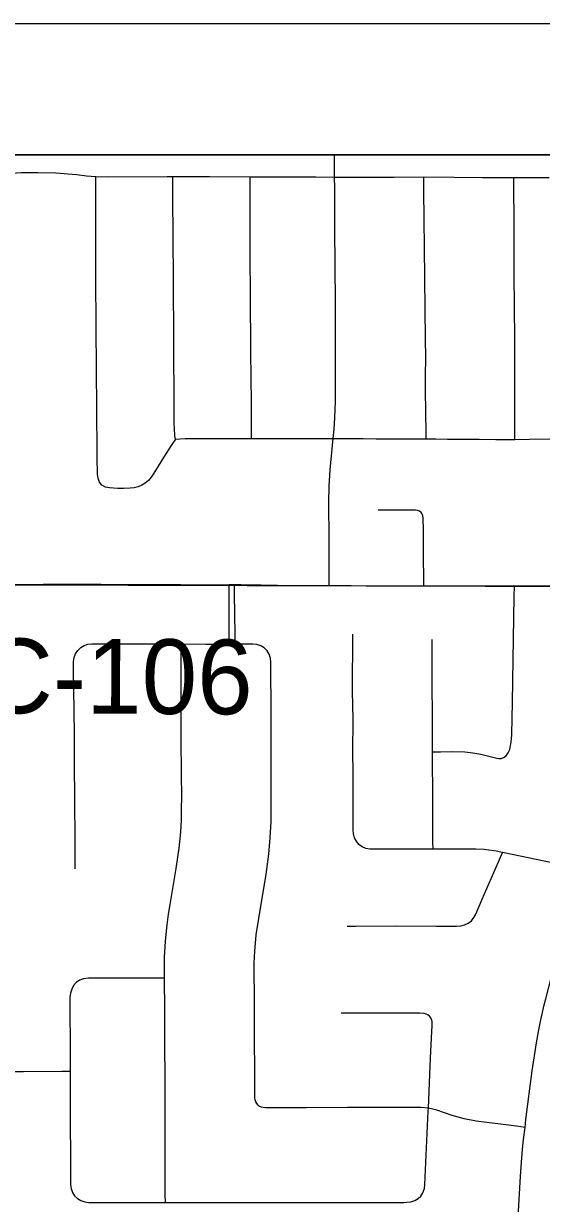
# Model space of a CAD drawing. Extents: x 0 to 34, y 0 to 22.
# Drawn here: x 19.27 to 19.665, y 15.179 to 16.078 of the extents above; entities that cross this region are included whole.
import ezdxf

# ---------------------------------------------------------------- set-up
doc = ezdxf.new("R2010")
doc.units = 0
for name, color, linetype in [('GM_X_City_Street', 7, 'Continuous'), ('GM_X_Corporation', 7, 'Continuous'), ('GM_X_County_Road', 7, 'Continuous'), ('GM_X_County_Road_Text', 7, 'Continuous'), ('GM_X_Section', 7, 'Continuous'), ('GM_X_Township_Road', 7, 'Continuous'), ('SH_Data', 7, 'Continuous')]:
    doc.layers.add(name, color=color, linetype=linetype)

msp = doc.modelspace()

# ---------------------------------------------------------------- linework, layer by layer
at = {"layer": 'GM_X_City_Street'}
for points in [[(19.503, 15.64975), (19.50299, 15.65426), (19.50287, 15.685), (19.50269, 15.71299), (19.50292, 15.72543), (19.50373, 15.73784), (19.50613, 15.76166), (19.50685, 15.76879), (19.50738, 15.77742), (19.50761, 15.78386), (19.5078, 15.78994), (19.5079, 15.79355), (19.50791, 15.80243), (19.50792, 15.82298), (19.50771, 15.86522), (19.50732, 15.92123), (19.50721, 15.9523), (19.50716, 15.96064), (19.50706, 15.97618), (19.50706, 15.97752)], [(19.29503, 15.96385), (19.29847, 15.96365), (19.30416, 15.96314), (19.31096, 15.96253), (19.31827, 15.96175), (19.32191, 15.96148), (19.32543, 15.96122), (19.33488, 15.96098), (19.37976, 15.96116), (19.38408, 15.96115), (19.4122, 15.96111), (19.44281, 15.96084), (19.44626, 15.96081), (19.49272, 15.96076), (19.50716, 15.96064), (19.5273, 15.96068), (19.54194, 15.96072), (19.55246, 15.96074), (19.57514, 15.96079), (19.59802, 15.96062), (19.61972, 15.96045), (19.64137, 15.96029), (19.64351, 15.96029), (19.67054, 15.96039)], [(19.38608, 15.76111), (19.38334, 15.75721), (19.37822, 15.74936), (19.36947, 15.73536), (19.36749, 15.73224), (19.36537, 15.72982), (19.36306, 15.72775), (19.36043, 15.72609), (19.35756, 15.72489), (19.35453, 15.72419), (19.35143, 15.72389), (19.34661, 15.72369), (19.3421, 15.72376), (19.3359, 15.72412), (19.33283, 15.72465), (19.3301, 15.7261), (19.32817, 15.72851), (19.32712, 15.73143), (19.32666, 15.73451), (19.32657, 15.73762), (19.32638, 15.74409), (19.32646, 15.7532), (19.3262, 15.78123), (19.32592, 15.81776), (19.32573, 15.84309), (19.32539, 15.88782), (19.32539, 15.90443), (19.32539, 15.91347), (19.32539, 15.92301), (19.32539, 15.95258), (19.32543, 15.96122)], [(19.38608, 15.76111), (19.38565, 15.76338), (19.38544, 15.76505), (19.38526, 15.76798), (19.3851, 15.77455), (19.38514, 15.78591), (19.38454, 15.88333), (19.38396, 15.94588), (19.38403, 15.95526), (19.38408, 15.96115)], [(19.44378, 15.76169), (19.4438, 15.7661), (19.44382, 15.7692), (19.44388, 15.77856), (19.44378, 15.79017), (19.44365, 15.80711), (19.44349, 15.82845), (19.44333, 15.84346), (19.44321, 15.85579), (19.44307, 15.86899), (19.44303, 15.87865), (19.44297, 15.89296), (19.4429, 15.91267), (19.44288, 15.92206), (19.44285, 15.93719), (19.44283, 15.95317), (19.44281, 15.96084)], [(19.57683, 15.76137), (19.57674, 15.76842), (19.57658, 15.77975), (19.57651, 15.78535), (19.57642, 15.79489), (19.57638, 15.79928), (19.57638, 15.80591), (19.57637, 15.81169), (19.57646, 15.821), (19.57602, 15.8582), (19.5758, 15.88606), (19.57557, 15.90491), (19.57548, 15.91214), (19.57534, 15.92324), (19.57523, 15.93451), (19.57514, 15.94483), (19.57514, 15.95556), (19.57514, 15.96079)], [(19.64441, 15.76096), (19.64439, 15.76874), (19.64433, 15.80603), (19.64423, 15.83714), (19.64405, 15.86202), (19.64383, 15.8869), (19.64387, 15.92422), (19.64355, 15.9555), (19.64351, 15.96029)], [(19.38608, 15.76111), (19.38936, 15.76156), (19.39329, 15.76171), (19.40848, 15.76177), (19.43972, 15.7617), (19.44378, 15.76169), (19.4555, 15.76166), (19.48952, 15.76166), (19.50613, 15.76166), (19.5105, 15.7617), (19.51682, 15.76167), (19.52882, 15.76161), (19.53869, 15.76156), (19.5553, 15.76148), (19.57683, 15.76137), (19.58408, 15.76133), (19.59312, 15.76128), (19.60415, 15.76121), (19.61713, 15.76113), (19.6298, 15.76105), (19.64441, 15.76096), (19.6555, 15.7612), (19.67096, 15.76134)], [(19.57501, 15.64949), (19.57497, 15.65305), (19.57491, 15.66135), (19.57488, 15.66498), (19.57482, 15.67216), (19.57477, 15.67915), (19.57472, 15.68428), (19.57466, 15.69172), (19.57459, 15.70116), (19.5743, 15.70274), (19.57402, 15.70372), (19.57361, 15.70455), (19.57304, 15.70537), (19.57163, 15.70633), (19.57029, 15.70681), (19.56861, 15.7071), (19.5597, 15.70715), (19.55402, 15.70718), (19.54721, 15.70722), (19.54032, 15.70727)], [(19.42683, 15.60519), (19.42683, 15.61102), (19.42685, 15.64383), (19.42685, 15.65044)], [(19.4315, 15.60519), (19.4314, 15.61241), (19.43099, 15.64336), (19.43089, 15.65046)], [(19.58171, 15.52319), (19.58766, 15.52327), (19.59694, 15.52338), (19.60622, 15.52307), (19.61237, 15.5224), (19.61847, 15.52129), (19.6305, 15.51833), (19.6321, 15.51812), (19.63389, 15.51821), (19.63561, 15.51884), (19.63765, 15.52024), (19.63934, 15.52249), (19.64046, 15.52493), (19.64109, 15.52806), (19.64153, 15.53053), (19.64181, 15.5332), (19.64203, 15.53628), (19.64248, 15.56106), (19.64387, 15.64155), (19.644, 15.64963)], [(19.69285, 15.43411), (19.68862, 15.43509), (19.67867, 15.4374), (19.66653, 15.43992), (19.64226, 15.44512), (19.63495, 15.44664), (19.63011, 15.44764), (19.6209, 15.44887), (19.61471, 15.44921), (19.58203, 15.44917), (19.57438, 15.44916), (19.53404, 15.44922), (19.53099, 15.44973), (19.52814, 15.45087), (19.52566, 15.4527), (19.52368, 15.45508), (19.52232, 15.45785), (19.52155, 15.46085), (19.52128, 15.46394), (19.52134, 15.50738), (19.52109, 15.52289), (19.52113, 15.54771), (19.52083, 15.56943), (19.5209, 15.61286)], [(19.58203, 15.44917), (19.582, 15.45472), (19.5818, 15.48859), (19.58172, 15.51939), (19.58171, 15.52319), (19.58168, 15.54096), (19.58145, 15.5841), (19.58134, 15.60874)], [(19.3097, 15.43416), (19.30956, 15.45577), (19.30939, 15.48672), (19.30918, 15.51456), (19.30923, 15.53622), (19.30891, 15.55478), (19.30874, 15.57024), (19.30847, 15.58569), (19.30843, 15.59188), (19.30892, 15.59492), (19.31001, 15.5978), (19.31168, 15.6004), (19.31387, 15.60256), (19.31651, 15.60415), (19.31943, 15.60508), (19.32249, 15.60544), (19.33486, 15.60537), (19.38738, 15.60537), (19.39048, 15.60535), (19.40902, 15.60527), (19.42683, 15.60519), (19.4315, 15.60519)], [(19.38083, 15.39972), (19.3819, 15.40688), (19.38658, 15.43443), (19.38887, 15.44979), (19.39007, 15.46216), (19.3905, 15.47147), (19.39064, 15.47937), (19.39074, 15.48933), (19.39066, 15.50566), (19.39042, 15.53358), (19.39038, 15.55486), (19.39035, 15.57376), (19.39046, 15.60201), (19.39048, 15.60535)], [(19.65204, 15.23735), (19.64562, 15.23814), (19.6148, 15.24195), (19.60566, 15.24374), (19.59671, 15.24628), (19.58497, 15.25038), (19.58199, 15.25127), (19.57855, 15.25194), (19.57279, 15.25255), (19.55725, 15.25258), (19.51683, 15.25235), (19.48575, 15.25232), (19.47331, 15.25227), (19.45461, 15.25216), (19.45288, 15.25237), (19.45157, 15.25272), (19.45008, 15.25333), (19.44892, 15.25424), (19.44784, 15.25553), (19.44712, 15.2567), (19.44656, 15.25824), (19.44636, 15.25969), (19.44633, 15.26592), (19.44635, 15.28146), (19.44617, 15.30321), (19.44608, 15.33118), (19.44595, 15.36227), (19.44634, 15.37158), (19.44755, 15.38395), (19.4494, 15.39624), (19.4551, 15.42996), (19.45709, 15.44537), (19.45815, 15.45775), (19.45872, 15.47017), (19.45891, 15.47979), (19.45887, 15.50125), (19.45875, 15.55098), (19.45861, 15.59138), (19.45824, 15.59446), (19.45731, 15.59742), (19.45573, 15.60007), (19.45353, 15.60225), (19.45089, 15.60383), (19.44796, 15.60478), (19.44488, 15.6052), (19.4315, 15.60519)], [(19.51677, 15.39045), (19.52294, 15.39056), (19.55376, 15.39062), (19.58458, 15.39058), (19.6, 15.39045), (19.60307, 15.39072), (19.60604, 15.39146), (19.60883, 15.39277), (19.61126, 15.39465), (19.61317, 15.39705), (19.61465, 15.39975), (19.61951, 15.41108), (19.63179, 15.43935), (19.63495, 15.44664)], [(19.3784, 15.18021), (19.3783, 15.18655), (19.37825, 15.18965), (19.37814, 15.24869), (19.37807, 15.27044), (19.37809, 15.28288), (19.37796, 15.2922), (19.378, 15.30463), (19.37783, 15.32639), (19.37768, 15.35087), (19.37765, 15.35437), (19.37768, 15.3667), (19.37837, 15.37919), (19.37962, 15.39154), (19.38083, 15.39972)], [(19.37768, 15.35087), (19.3718, 15.35089), (19.34388, 15.35097), (19.32528, 15.35079), (19.31985, 15.35079), (19.31599, 15.35033), (19.31309, 15.34929), (19.31055, 15.34757), (19.3085, 15.34527), (19.30705, 15.34255), (19.30615, 15.33959), (19.3057, 15.33653), (19.30555, 15.33031), (19.30585, 15.29623), (19.30578, 15.28005), (19.30577, 15.27761), (19.306, 15.25589), (19.30601, 15.20003), (19.30611, 15.19377), (19.30661, 15.1907), (19.30764, 15.18781), (19.30926, 15.18522), (19.31144, 15.1831), (19.31408, 15.18157), (19.31701, 15.18064), (19.32009, 15.18023), (19.3784, 15.18021), (19.44106, 15.1802), (19.46587, 15.1802), (19.49069, 15.18005), (19.52172, 15.18016), (19.54033, 15.18026), (19.55585, 15.18023), (19.55976, 15.18026), (19.56222, 15.18036), (19.56512, 15.1807), (19.56808, 15.18161), (19.57077, 15.18316), (19.57275, 15.18497), (19.57439, 15.18743), (19.57548, 15.19085), (19.57586, 15.19393), (19.57845, 15.24973), (19.57855, 15.25194), (19.57967, 15.27765), (19.58006, 15.29003), (19.58094, 15.30552), (19.58136, 15.31482), (19.58131, 15.31793), (19.58096, 15.31954), (19.58028, 15.3208), (19.57929, 15.322), (19.57807, 15.32291), (19.57673, 15.3236), (19.57519, 15.32399), (19.5721, 15.32432), (19.5121, 15.32427)], [(19.26064, 15.27981), (19.27032, 15.27996), (19.29948, 15.28004), (19.30578, 15.28005)]]:
    msp.add_lwpolyline(points, dxfattribs=at)
at = {"layer": 'GM_X_Corporation'}
msp.add_lwpolyline([(22.22398, 15.97752), (18.62557, 15.97752)], dxfattribs=at)
at = {"layer": 'GM_X_County_Road'}
for points in [[(19.25949, 15.65063), (19.28569, 15.65072), (19.32942, 15.6507), (19.37942, 15.6505), (19.38982, 15.65049)], [(19.38982, 15.65049), (19.41405, 15.65038), (19.42685, 15.65044)], [(19.42685, 15.65044), (19.43089, 15.65046), (19.43581, 15.65048), (19.45136, 15.65024), (19.47619, 15.64984), (19.503, 15.64975)], [(19.503, 15.64975), (19.5197, 15.64969), (19.57501, 15.64949)], [(19.57501, 15.64949), (19.58808, 15.64944), (19.644, 15.64963)], [(19.644, 15.64963), (19.67201, 15.64973), (19.67803, 15.64984)], [(19.65204, 15.23735), (19.65275, 15.24334), (19.65753, 15.28029), (19.66074, 15.30177), (19.66261, 15.3117), (19.66376, 15.318), (19.66525, 15.32474), (19.6664, 15.32968), (19.66781, 15.33516), (19.68345, 15.39521), (19.6909, 15.42533), (19.69285, 15.43411)], [(19.63882, 15.11941), (19.63983, 15.12094), (19.64102, 15.12323), (19.64225, 15.12607), (19.64316, 15.12903), (19.64386, 15.13204), (19.64484, 15.13817), (19.64562, 15.14744), (19.6468, 15.16914), (19.64854, 15.19994), (19.64926, 15.21095), (19.65009, 15.22065), (19.65096, 15.22808), (19.65204, 15.23735)]]:
    msp.add_lwpolyline(points, dxfattribs=at)
at = {"layer": 'GM_X_Section'}
msp.add_lwpolyline([(20.25544, 15.64755), (20.26215, 14.63524), (19.25999, 14.63809), (19.25935, 15.65043)], close=True, dxfattribs=at)
at = {"layer": 'GM_X_Township_Road'}
msp.add_lwpolyline([(19.25742, 15.96371), (19.2595, 15.96377), (19.26507, 15.96394), (19.26885, 15.96406), (19.27428, 15.96409), (19.28131, 15.96412), (19.29503, 15.96385)], dxfattribs=at)
at = {"layer": 'SH_Data'}
for p, q in [((17.75791, 16.07752), (24.75791, 16.07752)), ((17.85791, 15.97752), (24.65791, 15.97752))]:
    msp.add_line(p, q, dxfattribs=at)

# ---------------------------------------------------------------- texts
at = {"layer": 'GM_X_County_Road_Text'}
msp.add_text('C-106', height=0.056818, rotation=359.72205, dxfattribs=at).set_placement((19.23774, 15.55272))

doc.saveas('drawing.dxf')
